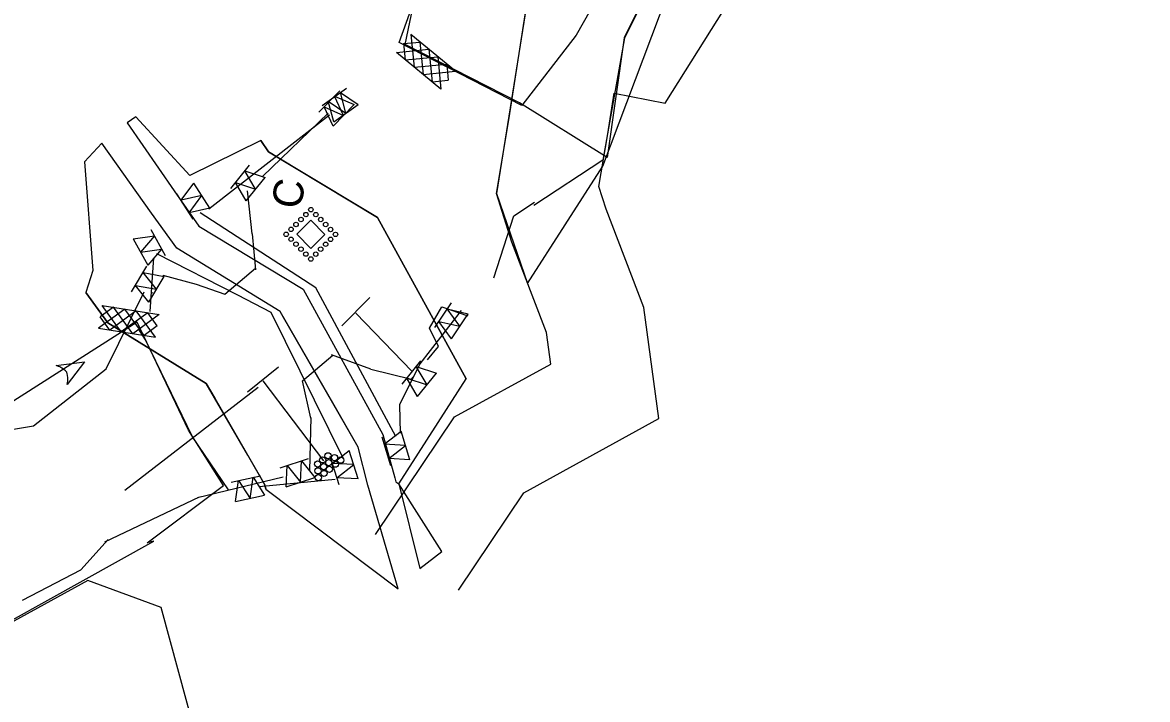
# Model space of a CAD drawing. Extents: x 2470000 to 2520000, y 340000 to 380000.
# Drawn here: x 2482633 to 2483197, y 367502 to 367841 of the extents above; entities that cross this region are included whole.
import ezdxf

# ---------------------------------------------------------------- set-up
doc = ezdxf.new("R2010")
doc.units = 0
for name, color, linetype in [('Bare Soil (Coastal) Drainage Area Border CandG Drainage', 7, 'Continuous'), ('Bare Soil (Coastal) Drainage Area Border FG Drainage', 7, 'Continuous'), ('Earth Berm for Slope Drains Final', 7, 'Continuous'), ('ESA Hatching CG', 7, 'Continuous'), ('Exist Property Owner Number CELL', 7, 'Continuous'), ('Exist Property Owner Text', 7, 'Continuous'), ('Exist Right of Way Easement Line', 7, 'Continuous'), ('Prop Guardrail', 7, 'Continuous'), ('Rock Silt Check Type A CG CELL', 7, 'Continuous'), ('Rock Silt Check Type A Final CELL', 7, 'Continuous'), ('Rock Silt Check Type B CG CELL', 7, 'Continuous'), ('Scratch_Level_4', 7, 'Continuous'), ('Scratch_Level_5', 7, 'Continuous'), ('Sheet Clip Boundary CELL', 7, 'Continuous'), ('Sheet Data Field CELL', 7, 'Continuous'), ('Special Sediment Control Fence Both', 7, 'Continuous'), ('Special Sediment Control Fence Section CG CELL', 7, 'Continuous'), ('Special Sediment Control Fence Section Final CELL', 7, 'Continuous'), ('Temporary Silt Fence CG', 7, 'Continuous'), ('Temporary Silt Fence Final', 7, 'Continuous')]:
    doc.layers.add(name, color=color, linetype=linetype)

# ---------------------------------------------------------------- blocks, each defined once
blk = doc.blocks.new('C3')
at = {"layer": 'Prop Guardrail'}
blk.add_text('C', height=0.3, dxfattribs=at).set_placement((-0.161, -0.136))

msp = doc.modelspace()

# ---------------------------------------------------------------- linework, layer by layer
at = {"layer": 'Bare Soil (Coastal) Drainage Area Border CandG Drainage'}
msp.add_lwpolyline([(2482886.45, 367953.41), (2482916.58, 367992.74), (2482949.4, 368071.88), (2482986.82, 368120.54), (2483017.82, 368208.47), (2483074.25, 368273.76), (2483121.41, 368365.22), (2483196.79, 368424.3), (2483128.64, 368254.09), (2483058.9, 368065.88), (2483043.08, 368010.64), (2483001.43, 367967.07), (2482934.61, 367833.16), (2482926.11, 367773.23), (2482882.08, 367800.67), (2482824.85, 367829.95), (2482832.71, 367867.61)], close=True, dxfattribs=at)
at = {"layer": 'Bare Soil (Coastal) Drainage Area Border FG Drainage'}
for points in [[(2483105.28, 368351.85), (2483032.56, 368134.42), (2483043.77, 368130.67), (2483013.12, 368039.02), (2483000.04, 368007.11), (2482957.66, 367917.74), (2482910.53, 367834.56), (2482883.4, 367799.36), (2482821.93, 367830.89), (2482829.2, 367851.28), (2482882.14, 367925.38), (2482906.02, 367971.16), (2482956.56, 368090.81), (2483010.12, 368230.8), (2483048.76, 368327.75), (2483075.3, 368347.99), (2483081.39, 368361.25)], [(2482695.58, 367580.14), (2482733.84, 367608.85), (2482716.34, 367636.65), (2482690.63, 367690.71), (2482545.08, 367598.01), (2482515.7, 367576.31), (2482522.38, 367567.27), (2482547.02, 367533.91), (2482573.34, 367511.14), (2482699.03, 367581.01)], [(2482595.21, 367166.32), (2482619.75, 367173.34), (2482682.86, 367212.09), (2482758.96, 367340.68), (2482702.55, 367547.73), (2482665.92, 367561.27), (2482576.36, 367512.28), (2482554.09, 367527.55), (2482480.29, 367482.43), (2482463.55, 367454.21), (2482466.48, 367427.48), (2482523.08, 367340.84), (2482562.66, 367271.9), (2482583.45, 367212.07), (2482598.79, 367167.93)]]:
    msp.add_lwpolyline(points, close=True, dxfattribs=at)
at = {"layer": 'Earth Berm for Slope Drains Final'}
msp.add_line((2482684.36, 367606.5), (2482751.22, 367658.25), dxfattribs=at)
at = {"layer": 'ESA Hatching CG'}
for points in [[(2483014.53, 368064.26), (2482985.23, 368000.82), (2482961.79, 367950.04), (2482955.63, 367920.94), (2482943.34, 367875.68), (2482930.97, 367856.06), (2482888.08, 367864.28), (2482870.64, 367755.17), (2482886.24, 367710.19), (2482923.93, 367768.93), (2482960.44, 367866.05), (2482960.44, 367866.05), (2482977.45, 367895.14), (2482991.03, 367919.95), (2483006.37, 367950.4), (2483019.07, 367979.49), (2483024.21, 367991.83), (2483029.44, 368004.57), (2483031.82, 368010.68), (2483040.06, 368032.75), (2483048.75, 368058.39), (2483050.92, 368064.66)], [(2482756.42, 367776.11), (2482752.54, 367781.7), (2482717.01, 367764.26), (2482689.87, 367793.65), (2482685.65, 367790.65), (2482709.14, 367756.54), (2482721.47, 367738.78), (2482773.76, 367707.36), (2482813.76, 367634.41), (2482819.68, 367612.68), (2482820.19, 367610.78), (2482821.78, 367609.73), (2482832.17, 367567.35), (2482843.18, 367575.91), (2482821.78, 367609.73), (2482855.5, 367662.29), (2482811.1, 367743.26), (2482769.63, 367768.15)], [(2482754.56, 367609.19), (2482755.08, 367607.15), (2482821.39, 367557.14), (2482806.17, 367609.13), (2482801.35, 367628.08), (2482763.98, 367693.07), (2482762.21, 367696.03), (2482710.53, 367727.77), (2482697.8, 367745.41), (2482672.87, 367780.41), (2482664.21, 367771.02), (2482668.47, 367716.63), (2482664.85, 367705.62), (2482675.83, 367690.41), (2482725.26, 367660.04), (2482729.58, 367652.72)]]:
    msp.add_lwpolyline(points, close=True, dxfattribs=at)
for points in [[(2482752.54, 367781.7), (2482756.42, 367776.11), (2482811.1, 367743.26), (2482855.5, 367662.29)], [(2482709.14, 367756.54), (2482721.47, 367738.78), (2482773.76, 367707.36), (2482813.76, 367634.41), (2482819.68, 367612.68)], [(2482806.17, 367609.13), (2482801.35, 367628.08), (2482789.35, 367649.11), (2482762.21, 367696.03), (2482710.53, 367727.77), (2482697.8, 367745.41)], [(2482755.08, 367607.15), (2482754.56, 367609.19), (2482746, 367624.2), (2482725.26, 367660.04), (2482675.83, 367690.41), (2482664.85, 367705.62)]]:
    msp.add_lwpolyline(points, dxfattribs=at)
at = {"layer": 'Exist Property Owner Number CELL'}
for p, q in [((2482800.21, 367695.33), (2482828.27, 367666.15)), ((2482753.56, 367661.41), (2482783.89, 367621.29))]:
    msp.add_line(p, q, dxfattribs=at)
at = {"layer": 'Exist Property Owner Text'}
for centre in [(2482786.23, 367623.8), (2482789.49, 367622.84), (2482780.98, 367619.69), (2482783.51, 367621.76), (2482784, 367618.39), (2482786.61, 367620.34), (2482786.91, 367617), (2482789.9, 367619.58), (2482792.61, 367621.62), (2482781.17, 367616.27), (2482781.36, 367612.84), (2482784.19, 367614.96)]:
    msp.add_circle(centre, 1.55, dxfattribs=at)
at = {"layer": 'Exist Right of Way Easement Line'}
for p, q in [((2482793.18, 367688.92), (2482807.23, 367703.16)), ((2482745.82, 367655.88), (2482761.45, 367668.36))]:
    msp.add_line(p, q, dxfattribs=at)
at = {"layer": 'Rock Silt Check Type A CG CELL'}
for p, q in [((2482684.47, 367697.31), (2482671.24, 367687.73)), ((2482678.68, 367698.19), (2482672.14, 367693.46)), ((2482673.06, 367699.14), (2482701.6, 367694.58)), ((2482682.64, 367685.91), (2482673.06, 367699.14)), ((2482688.37, 367684.99), (2482678.74, 367698.23)), ((2482694.05, 367684.09), (2482684.47, 367697.31)), ((2482676.92, 367686.82), (2482672.14, 367693.46)), ((2482690.19, 367696.4), (2482676.92, 367686.82)), ((2482695.87, 367695.51), (2482682.64, 367685.91)), ((2482701.6, 367694.58), (2482688.37, 367684.99)), ((2482699.78, 367683.17), (2482690.19, 367696.4)), ((2482700.7, 367688.9), (2482695.87, 367695.51)), ((2482671.24, 367687.73), (2482699.78, 367683.17)), ((2482700.7, 367688.9), (2482694.05, 367684.09))]:
    msp.add_line(p, q, dxfattribs=at)
at = {"layer": 'Rock Silt Check Type A Final CELL'}
for p, q in [((2482827.8, 367834.8), (2482829.38, 367818.55)), ((2482850.11, 367816.43), (2482827.8, 367834.8)), ((2482820.46, 367825.89), (2482836.72, 367827.46)), ((2482824.11, 367830.34), (2482832.28, 367831.12)), ((2482824.11, 367830.34), (2482824.93, 367822.19)), ((2482832.28, 367831.12), (2482833.85, 367814.86)), ((2482836.72, 367827.46), (2482838.33, 367811.17)), ((2482842.77, 367807.52), (2482820.46, 367825.89)), ((2482824.93, 367822.19), (2482841.2, 367823.77)), ((2482841.2, 367823.77), (2482842.77, 367807.52)), ((2482829.38, 367818.55), (2482845.67, 367820.09)), ((2482833.85, 367814.86), (2482850.11, 367816.43)), ((2482845.67, 367820.09), (2482846.43, 367811.95)), ((2482838.4, 367811.18), (2482846.43, 367811.95))]:
    msp.add_line(p, q, dxfattribs=at)
at = {"layer": 'Rock Silt Check Type B CG CELL'}
msp.add_lwpolyline([(2482649.99, 367668.97), (2482664.25, 367670.94), (2482655.55, 367659.48), (2482655.69, 367660.32), (2482655.86, 367661.33), (2482655.88, 367662.21), (2482655.85, 367662.83), (2482655.67, 367664.12), (2482655.5, 367664.9), (2482655.32, 367665.71), (2482654.73, 367666.32), (2482653.83, 367667.06), (2482653.24, 367667.5), (2482652.88, 367667.7), (2482652.43, 367667.97), (2482651.81, 367668.31), (2482651.23, 367668.53), (2482650.49, 367668.81)], close=True, dxfattribs=at)
at = {"layer": 'Scratch_Level_4'}
for points in [[(2482810.09, 367584.39), (2482849.56, 367643.26), (2482897.82, 367669.79), (2482895.68, 367685.54), (2482878.31, 367730.88), (2482870.64, 367755.17), (2482877, 367793.07), (2482888.08, 367864.28), (2482930.97, 367856.06), (2482942.65, 367874.61), (2482943.34, 367875.68), (2482955.63, 367920.94), (2482961.79, 367950.04), (2482985.23, 368000.82), (2483014.53, 368064.26), (2483085.04, 368065.06)], [(2482851.62, 367556.54), (2482884.32, 367605.31), (2482951.98, 367642.51), (2482944.45, 367698.02), (2482925.53, 367747.36), (2482921.94, 367758.75), (2482926.36, 367785.1), (2482929.52, 367805.43), (2482955.1, 367800.53), (2482984.81, 367847.73), (2482989.56, 367855.08), (2483004.25, 367909.2), (2483009.54, 367934.18), (2483030.63, 367979.86), (2483046.68, 368014.62), (2483061.92, 368014.79), (2483098.83, 368010.77)]]:
    msp.add_lwpolyline(points, dxfattribs=at)
at = {"layer": 'Scratch_Level_5'}
msp.add_lwpolyline([(2482777.61, 367727.7), (2482770.55, 367734.78), (2482777.64, 367741.84), (2482784.69, 367734.75)], close=True, dxfattribs=at)
for centre in [(2482777.64, 367747.13), (2482772.68, 367742.19), (2482775.16, 367744.66), (2482780.11, 367744.65), (2482782.58, 367742.17), (2482767.72, 367737.24), (2482770.2, 367739.72), (2482785.05, 367739.69), (2482787.52, 367737.21), (2482765.24, 367734.77), (2482767.71, 367732.29), (2482770.18, 367729.82), (2482785.03, 367729.79), (2482787.51, 367732.26), (2482789.99, 367734.73), (2482772.66, 367727.34), (2482775.13, 367724.86), (2482780.08, 367724.85), (2482782.55, 367727.32), (2482777.6, 367722.38)]:
    msp.add_circle(centre, 1.12, dxfattribs=at)
at = {"layer": 'Sheet Clip Boundary CELL'}
msp.add_lwpolyline([(2482736.38, 367606.83), (2482718.41, 367633.27), (2482694.84, 367681.95), (2482691.24, 367687.37)], dxfattribs=at)
at = {"layer": 'Sheet Data Field CELL'}
for p, q in [((2482879.28, 367743.95), (2482889.68, 367750.85)), ((2482869.23, 367712.98), (2482879.28, 367743.95))]:
    msp.add_line(p, q, dxfattribs=at)
at = {"layer": 'Special Sediment Control Fence Both'}
msp.add_lwpolyline([(2483042.05, 368008.46), (2483002.85, 367969.49), (2482934.73, 367833.23), (2482923.96, 367772), (2482889.27, 367749.26)], dxfattribs=at)
at = {"layer": 'Special Sediment Control Fence Section CG CELL'}
for p, q in [((2482781.66, 367795.96), (2482792.11, 367806.72)), ((2482788.84, 367789), (2482799.29, 367799.76)), ((2482727.08, 367747.84), (2482718.97, 367760.46)), ((2482718.67, 367742.44), (2482710.55, 367755.05)), ((2482697.42, 367737.26), (2482704.64, 367724.12)), ((2482688.65, 367732.44), (2482695.88, 367719.3)), ((2482839.71, 367688.02), (2482848.08, 367700.47)), ((2482848.01, 367682.44), (2482856.38, 367694.89)), ((2482827.28, 367621.79), (2482822.83, 367636.12)), ((2482817.73, 367618.83), (2482813.28, 367633.15)), ((2482801.39, 367612.23), (2482796.85, 367626.53)), ((2482791.86, 367609.2), (2482787.32, 367623.5)), ((2482737.69, 367610.63), (2482752.35, 367613.82)), ((2482739.82, 367600.86), (2482754.48, 367604.05))]:
    msp.add_line(p, q, dxfattribs=at)
for points in [[(2482794.06, 367794.38), (2482789.5, 367804.03), (2482799.29, 367799.76)], [(2482788.84, 367789), (2482784.28, 367798.65), (2482794.06, 367794.38)], [(2482723.02, 367754.15), (2482712.58, 367751.9), (2482718.97, 367760.46)], [(2482727.08, 367747.84), (2482716.64, 367745.59), (2482723.02, 367754.15)], [(2482688.65, 367732.44), (2482699.22, 367733.98), (2482692.27, 367725.87)], [(2482692.27, 367725.87), (2482702.84, 367727.4), (2482695.88, 367719.3)], [(2482852.19, 367688.67), (2482845.98, 367697.36), (2482856.38, 367694.89)], [(2482848.01, 367682.44), (2482841.8, 367691.14), (2482852.19, 367688.67)], [(2482825.06, 367628.96), (2482814.39, 367629.57), (2482822.83, 367636.12)], [(2482799.12, 367619.38), (2482788.45, 367619.92), (2482796.85, 367626.53)], [(2482827.28, 367621.79), (2482816.62, 367622.41), (2482825.06, 367628.96)], [(2482801.39, 367612.23), (2482790.72, 367612.78), (2482799.12, 367619.38)], [(2482747.15, 367602.45), (2482748.69, 367613.02), (2482754.48, 367604.05)], [(2482739.82, 367600.86), (2482741.36, 367611.42), (2482747.15, 367602.45)]]:
    msp.add_lwpolyline(points, dxfattribs=at)
at = {"layer": 'Special Sediment Control Fence Section Final CELL'}
for p, q in [((2482783.32, 367799.25), (2482795.53, 367807.96)), ((2482789.13, 367791.11), (2482801.34, 367799.81)), ((2482737.47, 367757.8), (2482746.88, 367769.47)), ((2482745.25, 367751.52), (2482754.67, 367763.2)), ((2482687.79, 367705.96), (2482695.5, 367718.83)), ((2482696.37, 367700.83), (2482704.08, 367713.69)), ((2482823.34, 367659.77), (2482832.75, 367671.45)), ((2482831.12, 367653.5), (2482840.54, 367665.17)), ((2482762.19, 367617.77), (2482776.45, 367622.42)), ((2482765.3, 367608.26), (2482779.56, 367612.92))]:
    msp.add_line(p, q, dxfattribs=at)
for points in [[(2482795.23, 367795.46), (2482792.48, 367805.78), (2482801.34, 367799.81)], [(2482789.13, 367791.11), (2482786.37, 367801.43), (2482795.23, 367795.46)], [(2482749.96, 367757.36), (2482744.53, 367766.55), (2482754.67, 367763.2)], [(2482745.25, 367751.52), (2482739.82, 367760.72), (2482749.96, 367757.36)], [(2482700.22, 367707.26), (2482693.57, 367715.62), (2482704.08, 367713.69)], [(2482696.37, 367700.83), (2482689.72, 367709.18), (2482700.22, 367707.26)], [(2482835.83, 367659.34), (2482830.4, 367668.53), (2482840.54, 367665.17)], [(2482831.12, 367653.5), (2482825.69, 367662.69), (2482835.83, 367659.34)], [(2482765.3, 367608.26), (2482765.76, 367618.93), (2482772.43, 367610.59)], [(2482772.43, 367610.59), (2482772.89, 367621.26), (2482779.56, 367612.92)]]:
    msp.add_lwpolyline(points, dxfattribs=at)
at = {"layer": 'Temporary Silt Fence CG'}
for p, q in [((2482786.94, 367794.42), (2482726.53, 367747.33)), ((2482698.83, 367722.91), (2482696.98, 367696.14)), ((2482751.78, 367608.35), (2482789.82, 367612.13))]:
    msp.add_line(p, q, dxfattribs=at)
for points in [[(2482820.26, 367633.42), (2482780.18, 367707.89), (2482722.17, 367745.57)], [(2482700.32, 367725.22), (2482740.84, 367704.37), (2482757.63, 367695.73), (2482793.75, 367622.4)], [(2482853, 367696.59), (2482832.17, 367669.87), (2482822.03, 367649.27), (2482822.4, 367635.09)]]:
    msp.add_lwpolyline(points, dxfattribs=at)
at = {"layer": 'Temporary Silt Fence Final'}
for p, q in [((2482753.33, 367763.71), (2482786.38, 367795.41)), ((2482748.26, 367734.94), (2482745.88, 367756.57)), ((2482748.26, 367734.94), (2482749.82, 367716.97)), ((2482703.49, 367714.29), (2482720.1, 367709.76)), ((2482734.47, 367704.85), (2482749.88, 367717.81)), ((2482720.1, 367709.76), (2482734.47, 367704.85)), ((2482675.04, 367667.29), (2482694.07, 367705.9)), ((2482698, 367705.23), (2482698.37, 367705.84)), ((2482773.42, 367661.3), (2482788.62, 367674.3)), ((2482807.72, 367667.17), (2482788, 367674.35)), ((2482638.63, 367638.89), (2482675.04, 367667.29)), ((2482807.72, 367667.17), (2482827.98, 367662.16)), ((2482777.54, 367642.68), (2482773.42, 367661.3)), ((2482777.55, 367643.03), (2482777, 367616.5)), ((2482620.05, 367635.68), (2482638.63, 367638.89)), ((2482720.91, 367602.97), (2482763.69, 367613.29)), ((2482776.76, 367616.44), (2482777, 367616.5)), ((2482674.45, 367580.66), (2482721.89, 367603.32)), ((2482662.33, 367566.7), (2482676, 367581.82)), ((2482633.19, 367551.46), (2482662.33, 367566.7))]:
    msp.add_line(p, q, dxfattribs=at)
for points in [[(2482836.09, 367671.95), (2482841.61, 367678.6), (2482837.11, 367687.74), (2482843.17, 367698.41), (2482856.22, 367694.01)], [(2482827.98, 367662.16), (2482828.87, 367663.23)]]:
    msp.add_lwpolyline(points, dxfattribs=at)

# ---------------------------------------------------------------- block references
at = {"layer": 'Scratch_Level_5', "xscale": 50, "yscale": 50, "rotation": 80.48585657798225}
msp.add_blockref('C3', (2482767.17, 367755.94), dxfattribs=at)

doc.saveas('drawing.dxf')
